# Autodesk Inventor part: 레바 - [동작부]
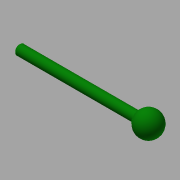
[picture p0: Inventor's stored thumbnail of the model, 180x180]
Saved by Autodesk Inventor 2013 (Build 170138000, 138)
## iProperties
Created: 2015-12
Part Number: 레바 - [동작부]
Material: 스테인리스강
Document SubType Name: Modeling
Designer: mduedu
Density: 8.08 g/cm^3
Mass: 30.7693 g
Surface Area: 20.8622 cm^2
Volume: 3.80808 cm^3
Author: mduedu
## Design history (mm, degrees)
sketch "스케치1"
  geometry: C1 r 3 at (0, 0); 1 further point
  constraints: 1 centre point, 1 coincident
  dimensions: "d0" = 6 diameter of C1
extrude "돌출1" new body sketch "스케치1" distance "d1" = 80; taper "d2" = 0 deg
sketch "스케치2"
  geometry: L1 (7.5, 0)-(-6, 0); L2 (-6, 4.5)-(-6, 0); A1 r 7.5 centre (0, 0) between (7.5, 0) and (-6, 4.5); 2 further points
  constraints: 4 end point, 2 coincident, 2 point on circle, 1 centre point, 1 horizontal, 1 perpendicular, 1 point on line
  dimensions: "d3" = 15 diameter of A1; "d10" = 6 distance from line of L2 point (0, 0)
revolve "회전1" sketch "스케치2" stored, may be unused: angle "d4" = 90 deg
chamfer "모따기1" distance "d7" = 0.5; stored, may be unused: second distance "d8" = 2, angle "d9" = 45 deg
fillet "모깎기2" dims "d11" = 0.3
node "솔리드1"
